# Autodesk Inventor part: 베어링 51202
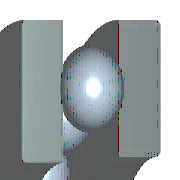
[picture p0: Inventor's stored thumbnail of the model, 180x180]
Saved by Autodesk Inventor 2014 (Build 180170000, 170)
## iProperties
Created: 2012-02
Part Number: 베어링 51202
Material: 강철, 연강
Description: 롤링 베어링 - 플랫 뒷면이 있는 스러스트 볼 베어링
Document SubType Name: Modeling
Standard: KS B 2022
Designer: mduedu
Standards Organization: KS
Language: ko-KR
Size Designation: 51202 - 15 x 32 x 12
Categories: <MemberInstance><Categories><Category DisplayName="샤프트 부품" InternalName="7f7aeb1f-a693-4053-b835-cee3144e0d98" Mnemonic="SHFT"><Category DisplayName="베어링" Inter
Density: 1 g/cm^3
Appearance: Dark Green
IsCustomPart: 1
Author: mduedu
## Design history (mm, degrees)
sketch "스케치1" dims "d3" = 5.28 (= 0.44 x KB)
  geometry: L1 (6, 9.61)-(6, 14.89); L2 (8.64, 12.25)-(3.36, 12.25); L3 (3.6, 16)-(0, 16); L4 (3.6, 7.5)-(0, 7.5); L5 (8.4, 13.35)-(8.4, 16); L6 (8.4, 16)-(12, 16); L7 (12, 16)-(12, 8.5); L8 (12, 8.5)-(8.4, 8.5); L9 (8.4, 8.5)-(8.4, 11.15); L10 (3.6, 16)-(3.6, 13.35); L11 (3.6, 11.15)-(3.6, 7.5); L12 (-1.8, 0)-(10.8, 0) reference; L13 (0, -0.022)-(0, 5.522) reference; 1 further point
  constraints: 22 end point, 5 perpendicular, 2 equal length, 2 midpoint, 2 parallel, 2 point on line, 1 collinear, 10 other
  dimensions: "d8" = 4.8 diameter of L11 L1 (= 0.4 x KB); "d11" = 15 diameter of L4 L12 (= WD); "d12" = 17 diameter of L8 L12 (= KAD1); "d13" = 32 diameter of L3 L12 (= KID1); "d14" = 32 diameter of L6 L12 (= BD); "d15" = 24.5 diameter of point (6, 12.25) L12 (= 0.5 x KID1 + 0.5 x KAD1); "d16" = 6 distance from line of point (6, 12.25) L13 (= 0.5 x KB); "d18" = 12 distance between parallel lines of L7 L13 (= KB)
revolve "본체" stored, may be unused: angle "d9" = 90 deg
revolve "볼" stored, may be unused: angle "d10" = 90 deg
pattern_circular "IDS_ARRAYBALL[SIMPL:T]" dims angle "d2" = 360 deg
body "Solid1"
fillet "모깎기1" dims "d4" = 0.6 (= KRS)
fillet "모깎기2" dims "d5" = 0.6 (= KRS)
other parameters: "WD" = 15 [user parameter; used in 2 equation terms], "KAD1" = 17 [user parameter; used in 3 equation terms], "KID1" = 32 [user parameter; used in 3 equation terms], "BD" = 32 [user parameter; used in 2 equation terms], "KB" = 12 [user parameter; used in 6 equation terms], "KRS" = 0.6 [user parameter; used in 2 equation terms], "d0" = 2.4 (= 0.2 x KB), "d6" = 0, "d7" = 0, "d19" = 0, "d41" = 0, "d42" = 0, "WR" = 7.5 (= 0.5 x WD) [user parameter], "BC" = 1.65e+07 [user parameter], "BBA" = 90 deg [user parameter], "BC0" = 2.7e+07 [user parameter], "BR" = 16 (= 0.5 x BD) [user parameter]
